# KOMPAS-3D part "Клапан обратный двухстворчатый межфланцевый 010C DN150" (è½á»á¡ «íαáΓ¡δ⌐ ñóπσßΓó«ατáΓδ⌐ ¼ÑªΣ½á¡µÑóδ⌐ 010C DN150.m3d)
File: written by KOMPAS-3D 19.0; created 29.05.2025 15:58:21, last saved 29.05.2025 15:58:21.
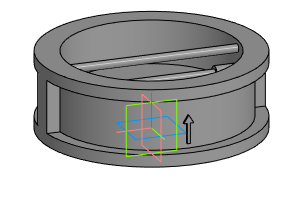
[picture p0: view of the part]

Document properties: Полное имя файла: E:\Dendor Работа Сачек\3D для проекитирвщиков\5.2 Тип 010C, 010C.Y Клапан обратный двухстворчатый межфланцевый\stp_Клапан обратный двухстворчатый межфланцевый 010C\Клапан обратный двухстворчатый межфланцевый 010C DN150.m3d

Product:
- Part/product: Клапан обратный двухстворчатый межфланцевый 010C DN150

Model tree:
1. Операция без истории:1  (labels: Клапан обратный двухстворчатый межфланцевый 010C DN150)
